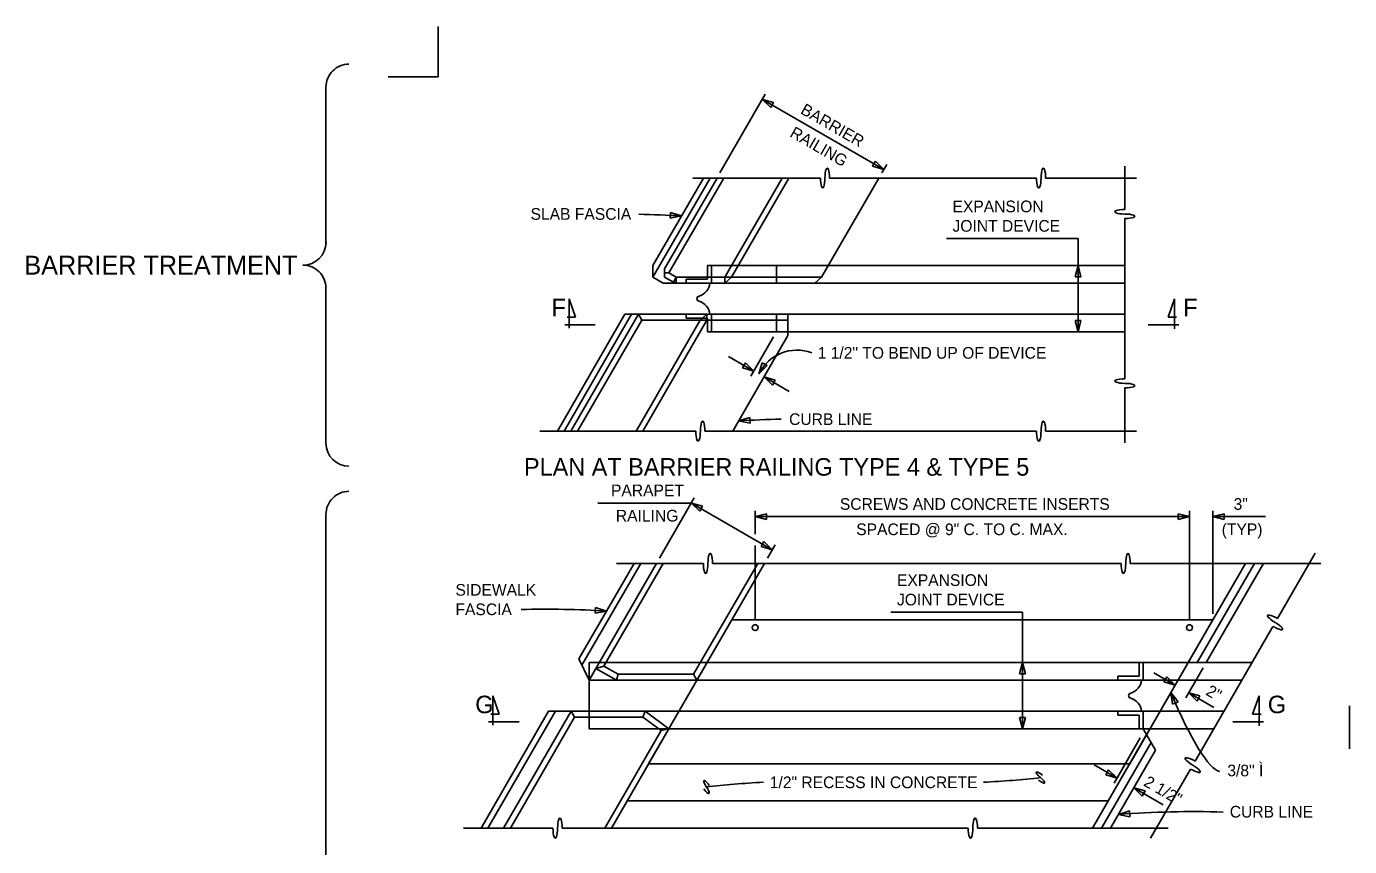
# Model space of a CAD drawing. Extents: x 19590 to 20151, y 19944 to 20103.
# Drawn here: x 19795.3 to 19847.7, y 20064.6 to 20097.1 of the extents above; entities that cross this region are included whole.
import ezdxf

# ---------------------------------------------------------------- set-up
doc = ezdxf.new("R2010")
doc.units = 0
for name, color, linetype in [('DETAIL_PR', 7, 'Continuous'), ('DETAIL_TEXT_DIMEN_PR', 7, 'Continuous'), ('Level 1', 7, 'Continuous'), ('Sheet_Label_Str_Wt0', 7, 'Continuous')]:
    doc.layers.add(name, color=color, linetype=linetype)

msp = doc.modelspace()

# ---------------------------------------------------------------- linework, layer by layer
at = {"layer": 'DETAIL_PR'}
for p, q in [((19811.624, 20097.101), (19811.624, 20095.111)), ((19809.634, 20095.111), (19811.624, 20095.111)), ((19822.391, 20091.099), (19820.121, 20087.168)), ((19822.124, 20091.099), (19820.121, 20087.63)), ((19822.658, 20091.099), (19820.584, 20087.506)), ((19822.925, 20091.099), (19820.753, 20087.337)), ((19821.697, 20091.099), (19826.75, 20091.099)), ((19825.239, 20091.099), (19822.97, 20087.168)), ((19825.506, 20091.099), (19823.237, 20087.168)), ((19829.067, 20091.099), (19826.797, 20087.168)), ((19827.114, 20091.099), (19835.307, 20091.099)), ((19835.67, 20091.099), (19839.266, 20091.099)), ((19838.803, 20091.562), (19838.803, 20089.855)), ((19838.803, 20089.491), (19838.803, 20084.855)), ((19820.121, 20087.168), (19820.121, 20087.63)), ((19820.584, 20087.168), (19820.584, 20087.506)), ((19822.288, 20087.091), (19822.288, 20087.63)), ((19822.288, 20087.63), (19827.153, 20087.63)), ((19822.442, 20086.937), (19822.442, 20087.63)), ((19825.017, 20086.937), (19825.017, 20087.63)), ((19827.153, 20087.63), (19838.803, 20087.63)), ((19820.121, 20087.168), (19820.522, 20086.937)), ((19820.522, 20086.937), (19821.44, 20086.937)), ((19820.753, 20087.337), (19820.584, 20087.337)), ((19820.584, 20087.168), (19820.931, 20086.968)), ((19820.753, 20087.337), (19821.046, 20087.168)), ((19821.046, 20087.168), (19820.931, 20086.968)), ((19820.931, 20086.968), (19821.046, 20086.937)), ((19821.046, 20087.168), (19826.797, 20087.168)), ((19821.046, 20086.937), (19821.046, 20087.168)), ((19821.44, 20086.937), (19821.44, 20087.091)), ((19821.44, 20087.091), (19822.288, 20087.091)), ((19821.44, 20086.937), (19838.803, 20086.937)), ((19822.97, 20086.937), (19822.97, 20087.168)), ((19823.237, 20087.168), (19822.97, 20086.937)), ((19826.797, 20087.168), (19826.53, 20086.937)), ((19819.009, 20085.703), (19816.339, 20081.078)), ((19819.276, 20085.703), (19816.606, 20081.078)), ((19819.543, 20085.703), (19816.873, 20081.078)), ((19819.676, 20085.472), (19817.14, 20081.078)), ((19819.009, 20085.703), (19822.307, 20085.703)), ((19821.991, 20085.472), (19819.454, 20081.078)), ((19819.543, 20085.703), (19819.677, 20085.472)), ((19819.677, 20085.472), (19825.462, 20085.472)), ((19822.258, 20085.472), (19819.721, 20081.078)), ((19821.44, 20085.703), (19821.44, 20085.549)), ((19821.44, 20085.703), (19838.803, 20085.703)), ((19821.44, 20085.549), (19822.288, 20085.549)), ((19822.258, 20085.703), (19821.991, 20085.472)), ((19822.258, 20085.472), (19822.258, 20085.703)), ((19822.288, 20085.549), (19822.288, 20085.009)), ((19822.442, 20085.703), (19822.442, 20085.009)), ((19825.017, 20085.009), (19825.017, 20085.703)), ((19825.462, 20084.855), (19825.462, 20085.703)), ((19822.288, 20085.009), (19825.462, 20085.009)), ((19825.462, 20084.855), (19823.281, 20081.078)), ((19825.462, 20085.009), (19838.803, 20085.009)), ((19838.803, 20083.149), (19838.803, 20084.855)), ((19838.803, 20082.785), (19838.803, 20080.616)), ((19815.645, 20081.078), (19821.817, 20081.078)), ((19822.181, 20081.078), (19835.307, 20081.078)), ((19835.67, 20081.078), (19839.265, 20081.078)), ((19846.336, 20076.238), (19844.846, 20073.657)), ((19819.373, 20075.837), (19817.192, 20072.06)), ((19819.64, 20075.837), (19817.312, 20071.805)), ((19820.263, 20075.837), (19817.592, 20071.212)), ((19820.53, 20075.837), (19818.179, 20071.765)), ((19818.679, 20075.837), (19822.118, 20075.837)), ((19824.268, 20075.837), (19821.731, 20071.443)), ((19824.535, 20075.837), (19821.865, 20071.212)), ((19822.481, 20075.837), (19838.657, 20075.837)), ((19839.021, 20075.837), (19846.567, 20075.837)), ((19843.583, 20075.837), (19841.313, 20071.906)), ((19843.939, 20075.837), (19841.669, 20071.906)), ((19844.295, 20075.837), (19842.025, 20071.906)), ((19823.245, 20073.602), (19819.951, 20067.897)), ((19823.245, 20073.602), (19842.292, 20073.602)), ((19842.292, 20073.602), (19838.999, 20067.897)), ((19844.664, 20073.341), (19841.584, 20068.006)), ((19817.192, 20072.06), (19817.592, 20071.212)), ((19817.592, 20071.906), (19822.266, 20071.906)), ((19817.592, 20071.212), (19817.592, 20071.906)), ((19817.592, 20071.906), (19841.313, 20071.906)), ((19818.179, 20071.765), (19817.862, 20071.679)), ((19818.682, 20071.212), (19817.862, 20071.679)), ((19818.744, 20071.443), (19818.179, 20071.765)), ((19839.379, 20071.366), (19839.379, 20071.906)), ((19839.533, 20071.212), (19839.533, 20071.906)), ((19841.313, 20071.906), (19843.835, 20071.906)), ((19817.592, 20069.979), (19817.592, 20071.212)), ((19817.592, 20071.212), (19821.865, 20071.212)), ((19818.744, 20071.443), (19818.682, 20071.212)), ((19818.744, 20071.443), (19821.731, 20071.443)), ((19821.731, 20071.443), (19821.865, 20071.212)), ((19821.865, 20071.212), (19840.913, 20071.212)), ((19838.531, 20071.212), (19838.531, 20071.366)), ((19838.531, 20071.366), (19839.379, 20071.366)), ((19840.913, 20071.212), (19843.435, 20071.212)), ((19847.702, 20068.492), (19847.702, 20070.188)), ((19815.99, 20069.979), (19813.319, 20065.354)), ((19816.257, 20069.979), (19813.587, 20065.354)), ((19816.88, 20069.979), (19814.209, 20065.354)), ((19817.014, 20069.747), (19814.477, 20065.354)), ((19815.99, 20069.979), (19817.592, 20069.979)), ((19817.014, 20069.747), (19816.88, 20069.979)), ((19817.014, 20069.747), (19819.72, 20069.747)), ((19817.592, 20069.285), (19817.592, 20069.979)), ((19817.592, 20069.979), (19821.153, 20069.979)), ((19819.72, 20069.747), (19819.815, 20069.979)), ((19819.72, 20069.747), (19820.443, 20069.212)), ((19819.815, 20069.979), (19820.752, 20069.285)), ((19821.153, 20069.979), (19840.201, 20069.979)), ((19838.531, 20069.979), (19838.531, 20069.825)), ((19838.531, 20069.824), (19839.379, 20069.824)), ((19839.379, 20069.825), (19839.379, 20069.285)), ((19839.533, 20069.979), (19839.533, 20069.285)), ((19840.201, 20069.979), (19842.723, 20069.979)), ((19817.592, 20069.285), (19820.752, 20069.285)), ((19817.592, 20069.285), (19839.8, 20069.285)), ((19820.443, 20069.212), (19818.215, 20065.354)), ((19820.752, 20069.285), (19818.482, 20065.354)), ((19820.443, 20069.212), (19820.752, 20069.285)), ((19839.666, 20069.053), (19837.53, 20065.354)), ((19839.533, 20069.285), (19840.023, 20068.437)), ((19839.8, 20069.285), (19842.322, 20069.285)), ((19839.844, 20068.745), (19837.886, 20065.354)), ((19840.023, 20068.437), (19838.242, 20065.354)), ((19819.951, 20067.897), (19838.999, 20067.897)), ((19841.402, 20067.691), (19839.821, 20064.953)), ((19819.105, 20066.433), (19838.153, 20066.433)), ((19812.626, 20065.354), (19816.164, 20065.354)), ((19816.528, 20065.354), (19832.605, 20065.354)), ((19832.969, 20065.354), (19840.515, 20065.354))]:
    msp.add_line(p, q, dxfattribs=at)
for centre in [(19824.17, 20073.293), (19841.367, 20073.293)]:
    msp.add_circle(centre, 0.116, dxfattribs=at)
for centre, radius, start, end in [((19821.765, 20087.001), 0.612, 288.1365, 353.9316), ((19821.964, 20086.32), 0.0999, 94.4387, 265.5613), ((19821.765, 20085.639), 0.612, 6.0684, 71.8635), ((19838.856, 20071.277), 0.612, 288.1365, 353.9316), ((19839.055, 20070.596), 0.0999, 94.4387, 265.5613), ((19838.856, 20069.914), 0.612, 6.0684, 71.8635)]:
    msp.add_arc(centre, radius, start, end, dxfattribs=at)
for centre, major_axis, ratio, start_param, end_param in [((19826.841, 20091.099), (0, -0.395), 0.230206, 4.712389, 7.853982), ((19827.023, 20091.099), (0, -0.395), 0.230204, 1.570796, 4.712389), ((19835.397, 20091.099), (0, -0.395), 0.230206, 4.712389, 7.853982), ((19835.579, 20091.099), (0, -0.395), 0.230204, 1.570796, 4.712389), ((19838.803, 20089.764), (0.395, 0), 0.230204, 1.570796, 4.712389), ((19838.803, 20089.582), (0.395, 0), 0.230206, 4.712389, 7.853982), ((19838.803, 20083.058), (0.395, 0), 0.230204, 1.570796, 4.712389), ((19838.803, 20082.876), (0.395, 0), 0.230206, 4.712389, 7.853982), ((19822.09, 20081.078), (0, -0.395), 0.230204, 1.570796, 4.712389), ((19835.579, 20081.078), (0, -0.395), 0.230204, 1.570796, 4.712389), ((19821.908, 20081.078), (0, -0.395), 0.230206, 4.712389, 7.853982), ((19835.397, 20081.078), (0, -0.395), 0.230206, 4.712389, 7.853982), ((19822.39, 20075.837), (0, -0.395), 0.230204, 1.570796, 4.712389), ((19838.93, 20075.837), (0, -0.395), 0.230204, 1.570796, 4.712389), ((19822.208, 20075.837), (0, -0.395), 0.230206, 4.712389, 7.853982), ((19838.748, 20075.837), (0, -0.395), 0.230206, 4.712389, 7.853982), ((19844.801, 20073.578), (0.342, -0.198), 0.230204, 1.570796, 4.712389), ((19844.71, 20073.42), (0.342, -0.198), 0.230206, 4.712389, 7.853982), ((19841.539, 20067.928), (0.342, -0.198), 0.230204, 1.570796, 4.712389), ((19835.502, 20067.398), (0.203, -0.168), 0.230204, 1.570796, 4.712389), ((19841.448, 20067.77), (0.342, -0.198), 0.230206, 4.712389, 7.853982), ((19822.293, 20067.012), (0.147, -0.219), 0.230204, 1.570796, 4.712389), ((19822.192, 20066.945), (0.147, -0.219), 0.230206, 4.712389, 7.853982), ((19835.424, 20067.305), (0.203, -0.168), 0.230206, 4.712389, 7.853982), ((19816.437, 20065.354), (0, -0.395), 0.230204, 1.570796, 4.712389), ((19832.878, 20065.354), (0, -0.395), 0.230204, 1.570796, 4.712389), ((19816.255, 20065.354), (0, -0.395), 0.230206, 4.712389, 7.853982), ((19832.696, 20065.354), (0, -0.395), 0.230206, 4.712389, 7.853982)]:
    msp.add_ellipse(centre, major_axis=major_axis, ratio=ratio, start_param=start_param, end_param=end_param, dxfattribs=at)
at = {"layer": 'DETAIL_TEXT_DIMEN_PR'}
for p, q in [((19807.176, 20094.698), (19807.176, 20088.514)), ((19822.774, 20091.299), (19824.571, 20094.413)), ((19824.456, 20094.213), (19829.262, 20091.438)), ((19829.182, 20091.299), (19829.378, 20091.638)), ((19831.741, 20088.709), (19836.953, 20088.709)), ((19836.953, 20088.709), (19836.953, 20085.009)), ((19807.176, 20086.737), (19807.176, 20080.595)), ((19816.799, 20085.149), (19816.798, 20086.32)), ((19816.798, 20086.32), (19817.051, 20085.584)), ((19840.768, 20086.32), (19840.515, 20085.584)), ((19840.768, 20085.122), (19840.768, 20086.32)), ((19817.051, 20085.584), (19816.721, 20085.584)), ((19840.515, 20085.584), (19840.846, 20085.584)), ((19817.839, 20085.279), (19816.633, 20085.279)), ((19824.003, 20083.253), (19824.901, 20084.809)), ((19839.728, 20085.279), (19840.943, 20085.279)), ((19823.117, 20084.032), (19824.119, 20083.454)), ((19824.519, 20083.223), (19825.52, 20082.645)), ((19817.942, 20078.226), (19821.642, 20078.226)), ((19820.378, 20076.037), (19821.758, 20078.426)), ((19821.642, 20078.226), (19824.847, 20076.376)), ((19807.176, 20077.779), (19807.176, 20063.131)), ((19824.17, 20076.989), (19824.17, 20077.918)), ((19824.17, 20077.687), (19841.367, 20077.687)), ((19841.367, 20073.602), (19841.367, 20077.918)), ((19842.292, 20073.833), (19842.292, 20077.918)), ((19842.292, 20077.687), (19844.374, 20077.687)), ((19824.17, 20073.602), (19824.17, 20076.544)), ((19824.651, 20076.037), (19824.962, 20076.576)), ((19829.542, 20073.91), (19834.754, 20073.91)), ((19834.754, 20073.91), (19834.754, 20069.285)), ((19841.218, 20070.508), (19841.91, 20071.705)), ((19840.8, 20071.017), (19839.949, 20071.508)), ((19841.334, 20070.708), (19842.335, 20070.13)), ((19813.78, 20069.424), (19813.78, 20070.595)), ((19813.78, 20070.595), (19814.032, 20069.859)), ((19844.119, 20070.595), (19843.866, 20069.859)), ((19844.118, 20069.397), (19844.119, 20070.595)), ((19814.032, 20069.859), (19813.702, 20069.859)), ((19843.866, 20069.859), (19844.197, 20069.859)), ((19814.82, 20069.555), (19813.614, 20069.555)), ((19843.079, 20069.555), (19844.294, 20069.555)), ((19838.379, 20067.132), (19839.417, 20068.93)), ((19837.594, 20067.853), (19838.495, 20067.332)), ((19839.162, 20066.947), (19840.32, 20066.279))]:
    msp.add_line(p, q, dxfattribs=at)
for centre, radius, start, end in [((19808.086, 20094.699), 0.91, 89.9663, 180.0337), ((19818.829, 20050.52), 39.151, 86.4465, 88.9222), ((19806.266, 20088.558), 0.911, 269.9663, 359.9663), ((19806.266, 20086.737), 0.91, 359.9663, 90.0337), ((19825.82, 20082.619), 1.664, 69.1378, 154.3845), ((19825.939, 20042.403), 39.151, 91.0778, 93.5535), ((19808.086, 20080.596), 0.91, 180.0337, 270.0337), ((19808.086, 20077.78), 0.91, 89.9663, 180.0337), ((19815.856, 20034.872), 39.151, 86.4465, 91.4029), ((19841.537, 20026.856), 39.151, 88.2954, 94.3693)]:
    msp.add_arc(centre, radius, start, end, dxfattribs=at)
at = {"layer": 'Level 1'}
for p, q in [((19824.456, 20094.212), (19824.901, 20094.089)), ((19824.786, 20093.888), (19824.456, 20094.212)), ((19824.901, 20094.089), (19824.786, 20093.888)), ((19828.932, 20091.762), (19828.816, 20091.562)), ((19829.262, 20091.437), (19828.932, 20091.762)), ((19828.816, 20091.562), (19829.262, 20091.437)), ((19820.815, 20089.736), (19820.802, 20089.505)), ((19820.802, 20089.505), (19821.256, 20089.596)), ((19821.256, 20089.596), (19820.815, 20089.736)), ((19836.837, 20087.183), (19836.953, 20087.63)), ((19836.953, 20087.63), (19837.069, 20087.183)), ((19837.069, 20087.183), (19836.837, 20087.183)), ((19837.068, 20085.457), (19836.837, 20085.457)), ((19836.837, 20085.457), (19836.953, 20085.009)), ((19836.953, 20085.009), (19837.068, 20085.457)), ((19823.788, 20083.778), (19823.673, 20083.578)), ((19824.118, 20083.454), (19823.788, 20083.778)), ((19824.443, 20083.784), (19824.319, 20083.338)), ((19824.643, 20083.668), (19824.443, 20083.784)), ((19823.673, 20083.578), (19824.118, 20083.454)), ((19824.319, 20083.338), (19824.643, 20083.668)), ((19824.519, 20083.223), (19824.964, 20083.099)), ((19824.849, 20082.899), (19824.519, 20083.223)), ((19824.964, 20083.099), (19824.849, 20082.899)), ((19823.513, 20081.479), (19823.953, 20081.619)), ((19823.953, 20081.619), (19823.966, 20081.388)), ((19823.966, 20081.388), (19823.513, 20081.479)), ((19821.642, 20078.226), (19822.088, 20078.102)), ((19821.972, 20077.902), (19821.642, 20078.226)), ((19822.088, 20078.102), (19821.972, 20077.902)), ((19824.618, 20077.803), (19824.17, 20077.687)), ((19824.17, 20077.687), (19824.618, 20077.571)), ((19824.618, 20077.571), (19824.618, 20077.803)), ((19841.367, 20077.687), (19840.919, 20077.803)), ((19840.919, 20077.803), (19840.919, 20077.571)), ((19840.919, 20077.571), (19841.367, 20077.687)), ((19842.292, 20077.687), (19842.74, 20077.803)), ((19842.74, 20077.571), (19842.292, 20077.687)), ((19842.74, 20077.803), (19842.74, 20077.571)), ((19824.401, 20076.5), (19824.517, 20076.7)), ((19824.846, 20076.376), (19824.401, 20076.5)), ((19824.517, 20076.7), (19824.846, 20076.376)), ((19817.842, 20074.089), (19817.828, 20073.858)), ((19817.828, 20073.858), (19818.282, 20073.948)), ((19818.282, 20073.948), (19817.842, 20074.089)), ((19834.754, 20071.906), (19834.638, 20071.458)), ((19834.87, 20071.458), (19834.754, 20071.906)), ((19834.638, 20071.458), (19834.87, 20071.458)), ((19840.47, 20071.341), (19840.354, 20071.14)), ((19840.354, 20071.14), (19840.8, 20071.017)), ((19840.8, 20071.017), (19840.47, 20071.341)), ((19840.628, 20070.718), (19840.911, 20070.352)), ((19840.698, 20070.261), (19840.628, 20070.718)), ((19841.78, 20070.584), (19841.334, 20070.708)), ((19841.334, 20070.708), (19841.664, 20070.384)), ((19840.911, 20070.352), (19840.698, 20070.261)), ((19841.664, 20070.384), (19841.78, 20070.584)), ((19834.869, 20069.733), (19834.638, 20069.733)), ((19834.638, 20069.733), (19834.754, 20069.285)), ((19834.754, 20069.285), (19834.869, 20069.733)), ((19838.049, 20067.456), (19838.164, 20067.656)), ((19838.164, 20067.656), (19838.495, 20067.332)), ((19838.495, 20067.332), (19838.049, 20067.456)), ((19839.162, 20066.947), (19839.492, 20066.623)), ((19839.608, 20066.823), (19839.162, 20066.947)), ((19839.492, 20066.623), (19839.608, 20066.823)), ((19838.554, 20065.894), (19838.995, 20066.034)), ((19838.995, 20066.034), (19839.008, 20065.803)), ((19839.008, 20065.803), (19838.554, 20065.894))]:
    msp.add_line(p, q, dxfattribs=at)
for centre, major_axis, start_param, end_param in [((19840.661, 20073.86), (2.009, -6.26), 5.183087, 6.19004), ((19825.145, 20066.081), (-6.57, -0.223), 4.805942, 5.164147), ((19832.561, 20068.255), (6.57, 0.223), 4.805942, 5.164147)]:
    msp.add_ellipse(centre, major_axis=major_axis, ratio=0.169331, start_param=start_param, end_param=end_param, dxfattribs=at)

# ---------------------------------------------------------------- texts
at = {"layer": 'DETAIL_TEXT_DIMEN_PR'}
for s, height, rotation, p in [('BARRIER', 0.4625, 330, (19825.928, 20093.675)), ('RAILING', 0.4625, 330, (19825.506, 20092.761)), ('BARRIER TREATMENT', 0.74643, 360, (19795.235, 20087.274)), ('2"', 0.4625, 330, (19841.976, 20070.65)), ('2 1/2"', 0.4625, 330, (19839.513, 20067.053))]:
    msp.add_text(s, height=height, rotation=rotation, dxfattribs=at).set_placement(p)
for s, height, p in [('EXPANSION ', 0.4625, (19831.982, 20089.743)), ('SLAB FASCIA', 0.4625, (19815.276, 20089.445)), ('JOINT DEVICE', 0.4625, (19831.982, 20088.972)), ('F', 0.694, (19816.105, 20085.626)), ('F', 0.694, (19841.115, 20085.626)), ('1 1/2" TO BEND UP OF DEVICE', 0.4625, (19826.644, 20083.943)), ('CURB LINE', 0.4625, (19825.512, 20081.317)), ('PLAN AT BARRIER RAILING TYPE 4 & TYPE 5', 0.69385, (19815.016, 20079.311)), ('PARAPET', 0.4625, (19818.461, 20078.496)), ('RAILING', 0.4625, (19818.653, 20077.494)), ('SCREWS AND CONCRETE INSERTS', 0.4625, (19827.522, 20077.957)), ('3"', 0.4625, (19843.112, 20077.957)), ('SPACED @ 9" C. TO C. MAX.', 0.4625, (19828.17, 20076.955)), ('(TYP)', 0.4625, (19842.641, 20076.955)), ('EXPANSION ', 0.4625, (19829.783, 20074.943)), ('SIDEWALK', 0.4625, (19812.302, 20074.557)), ('JOINT DEVICE', 0.4625, (19829.783, 20074.172)), ('FASCIA', 0.4625, (19812.302, 20073.786)), ('G', 0.694, (19813.086, 20069.902)), ('G', 0.694, (19844.466, 20069.902)), ('1/2" RECESS IN CONCRETE', 0.4625, (19824.748, 20066.934)), ('CURB LINE', 0.4625, (19842.96, 20065.77))]:
    msp.add_text(s, height=height, dxfattribs=at).set_placement(p)
at = {"layer": 'Sheet_Label_Str_Wt0'}
msp.add_text('3/8" Ì', height=0.4625, dxfattribs=at).set_placement((19842.864, 20067.402))

doc.saveas('drawing.dxf')
